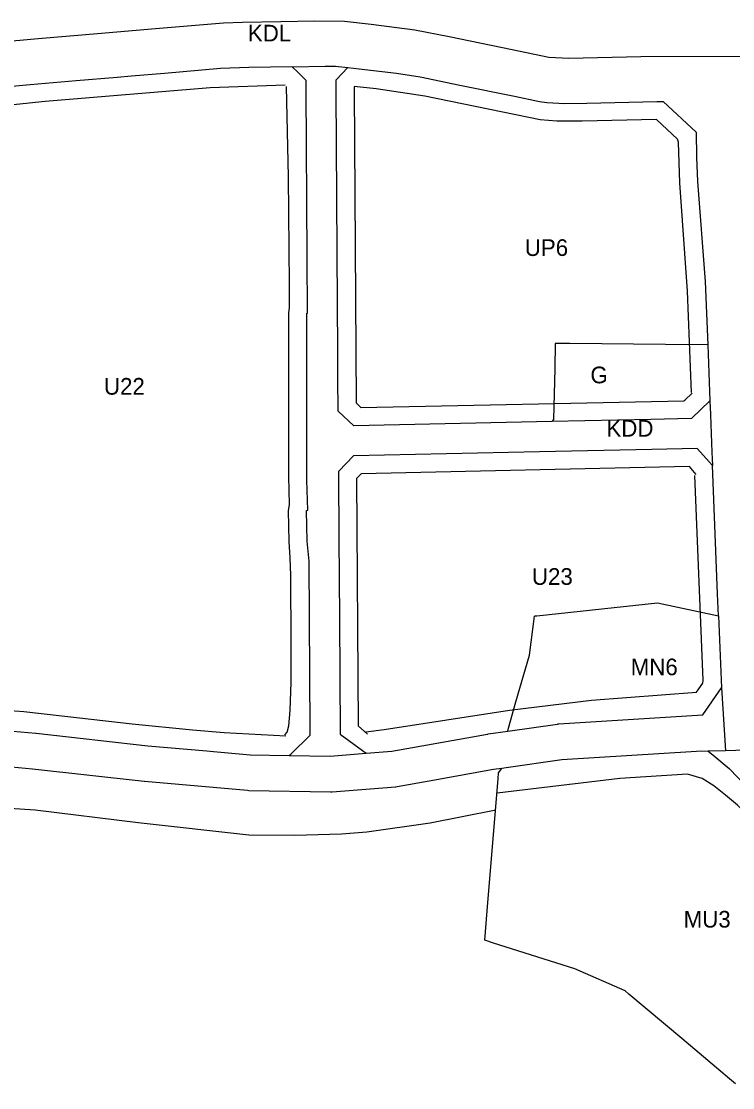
# Model space of a CAD drawing. Extents: x 7428080 to 7432143, y 5545880 to 5549217.
# Drawn here: x 7429649.7 to 7429886.6, y 5547932.8 to 5548287.9 of the extents above; entities that cross this region are included whole.
import ezdxf

# ---------------------------------------------------------------- set-up
doc = ezdxf.new("R2010")
doc.units = 0
for name, color, linetype in [('CZ_L_linie rozgraniczające tereny o różnym przeznaczeniu oraz różnych warunkach ich zabudowy i zagospodarowania', 7, 'Continuous'), ('CZ_L_maksymalne nieprzekraczalne linie zabudowy', 7, 'Continuous'), ('CZ_L_opisy_linie rozgraniczające tereny o różnym przeznaczeniu oraz różnych warunkach ich zabudowy i zagospodarowania', 7, 'Continuous')]:
    doc.layers.add(name, color=color, linetype=linetype)

msp = doc.modelspace()

# ---------------------------------------------------------------- linework, layer by layer
at = {"layer": 'CZ_L_linie rozgraniczające tereny o różnym przeznaczeniu oraz różnych warunkach ich zabudowy i zagospodarowania'}
for p, q in [((7429694.36, 5548285.36), (7429675.07, 5548283.73)), ((7429717.03, 5548287.27), (7429694.36, 5548285.36)), ((7429723.34, 5548287.55), (7429717.03, 5548287.27)), ((7429736.13, 5548287.76), (7429723.34, 5548287.55)), ((7429747.33, 5548287.89), (7429736.13, 5548287.76)), ((7429757.31, 5548287.88), (7429747.33, 5548287.89)), ((7429766.17, 5548286.78), (7429757.31, 5548287.88)), ((7429780.71, 5548284.89), (7429766.17, 5548286.78)), ((7429655.33, 5548282.07), (7429638.47, 5548280.52)), ((7429675.07, 5548283.73), (7429655.33, 5548282.07)), ((7429792.23, 5548282.72), (7429780.71, 5548284.89)), ((7429813.17, 5548278.42), (7429792.23, 5548282.72)), ((7429825.43, 5548275.82), (7429813.17, 5548278.42)), ((7429832.04, 5548275.52), (7429825.43, 5548275.82)), ((7429856.01, 5548276.02), (7429832.04, 5548275.52)), ((7429896.76, 5548276.15), (7429856.01, 5548276.02)), ((7429716.05, 5548272.14), (7429697.39, 5548270.56)), ((7429725.52, 5548272.55), (7429716.05, 5548272.14)), ((7429739.9, 5548272.77), (7429725.52, 5548272.55)), ((7429739.9, 5548272.77), (7429750.89, 5548272.94)), ((7429741.76, 5548270.94), (7429739.9, 5548272.77)), ((7429744.25, 5548268.5), (7429741.76, 5548270.94)), ((7429750.89, 5548272.94), (7429754.36, 5548272.91)), ((7429754.36, 5548272.91), (7429758.47, 5548272.5)), ((7429754.61, 5548268.4), (7429758.47, 5548272.5)), ((7429758.47, 5548272.5), (7429762.24, 5548272.12)), ((7429762.24, 5548272.12), (7429774.62, 5548270.6)), ((7429667.97, 5548268.08), (7429652.63, 5548266.79)), ((7429681.61, 5548269.23), (7429667.97, 5548268.08)), ((7429686.33, 5548269.63), (7429681.61, 5548269.23)), ((7429697.39, 5548270.56), (7429686.33, 5548269.63)), ((7429744.58, 5548268.17), (7429744.25, 5548268.5)), ((7429744.59, 5548265.02), (7429744.58, 5548268.17)), ((7429754.57, 5548268.33), (7429754.61, 5548268.4)), ((7429754.6, 5548264.4), (7429754.57, 5548268.33)), ((7429774.62, 5548270.6), (7429782.56, 5548269.4)), ((7429782.56, 5548269.4), (7429795.77, 5548266.68)), ((7429652.63, 5548266.79), (7429638.77, 5548265.45)), ((7429744.92, 5548209.33), (7429744.59, 5548265.02)), ((7429755.01, 5548193.74), (7429754.6, 5548264.4)), ((7429795.77, 5548266.68), (7429813.91, 5548262.93)), ((7429813.91, 5548262.93), (7429822.33, 5548261.15)), ((7429822.33, 5548261.15), (7429824.74, 5548260.84)), ((7429824.74, 5548260.84), (7429830.77, 5548260.56)), ((7429830.77, 5548260.56), (7429838.04, 5548260.62)), ((7429838.04, 5548260.62), (7429861.4, 5548261.14)), ((7429861.4, 5548261.14), (7429863.54, 5548261.2)), ((7429863.54, 5548261.2), (7429874.49, 5548250.98)), ((7429874.49, 5548250.98), (7429874.64, 5548242.67)), ((7429874.64, 5548242.67), (7429874.97, 5548234.56)), ((7429874.97, 5548234.56), (7429877.51, 5548201.27)), ((7429745.03, 5548190.75), (7429744.92, 5548209.33)), ((7429877.51, 5548201.27), (7429878.37, 5548180.2)), ((7429755.1, 5548178.47), (7429755.01, 5548193.74)), ((7429744.74, 5548190.74), (7429745.03, 5548190.75)), ((7429744.81, 5548172.97), (7429744.74, 5548190.74)), ((7429827.56, 5548180.61), (7429827.37, 5548172.29)), ((7429831.43, 5548180.58), (7429827.56, 5548180.61)), ((7429832.42, 5548180.57), (7429831.43, 5548180.58)), ((7429864.26, 5548180.31), (7429832.42, 5548180.57)), ((7429878.37, 5548180.2), (7429864.26, 5548180.31)), ((7429878.37, 5548180.2), (7429878.39, 5548180.2)), ((7429878.39, 5548180.2), (7429879.07, 5548161.45)), ((7429755.16, 5548169.12), (7429755.1, 5548178.47)), ((7429744.78, 5548155.01), (7429744.81, 5548172.97)), ((7429827.37, 5548172.29), (7429826.98, 5548155.26)), ((7429827.37, 5548172.29), (7429827.37, 5548172.29)), ((7429755.22, 5548158.09), (7429755.16, 5548169.12)), ((7429879.07, 5548161.45), (7429872.97, 5548155.6)), ((7429879.07, 5548161.45), (7429879.23, 5548156.91)), ((7429755.25, 5548158.07), (7429755.22, 5548158.09)), ((7429760.39, 5548153.18), (7429755.25, 5548158.07)), ((7429744.82, 5548135.11), (7429744.78, 5548155.01)), ((7429826.38, 5548154.6), (7429760.39, 5548153.18)), ((7429826.44, 5548154.6), (7429826.38, 5548154.6)), ((7429859.38, 5548155.31), (7429826.44, 5548154.6)), ((7429826.98, 5548155.26), (7429826.44, 5548154.6)), ((7429872.97, 5548155.6), (7429859.38, 5548155.31)), ((7429879.23, 5548156.91), (7429879.22, 5548156.89)), ((7429879.22, 5548156.89), (7429879.72, 5548144.43)), ((7429760.34, 5548143.18), (7429755.4, 5548138.09)), ((7429822.25, 5548144.51), (7429760.34, 5548143.18)), ((7429859.67, 5548145.31), (7429822.25, 5548144.51)), ((7429874.86, 5548145.64), (7429859.67, 5548145.31)), ((7429879.9, 5548139.96), (7429874.86, 5548145.64)), ((7429879.72, 5548144.43), (7429879.9, 5548139.96)), ((7429881.64, 5548097.22), (7429879.9, 5548139.96)), ((7429755.4, 5548138.09), (7429755.34, 5548138.02)), ((7429755.34, 5548138.02), (7429755.35, 5548137.21)), ((7429755.35, 5548137.21), (7429755.47, 5548115.72)), ((7429745.08, 5548125.11), (7429744.82, 5548135.11)), ((7429744.73, 5548125.02), (7429745.08, 5548125.11)), ((7429744.92, 5548114.8), (7429744.73, 5548125.02)), ((7429745.52, 5548108.07), (7429744.92, 5548114.8)), ((7429755.47, 5548115.72), (7429755.63, 5548089.2)), ((7429745.63, 5548089.1), (7429745.52, 5548108.07)), ((7429881.9, 5548089.88), (7429881.64, 5548097.22)), ((7429821.44, 5548089.88), (7429861.6, 5548094.22)), ((7429861.6, 5548094.22), (7429881.9, 5548089.88)), ((7429818.92, 5548076.81), (7429820.68, 5548089.84)), ((7429820.68, 5548089.84), (7429820.86, 5548089.85)), ((7429820.86, 5548089.85), (7429821.44, 5548089.88)), ((7429881.9, 5548089.88), (7429881.94, 5548089.87)), ((7429881.94, 5548089.87), (7429882.91, 5548065.97)), ((7429745.85, 5548051.97), (7429745.63, 5548089.1)), ((7429755.63, 5548089.2), (7429755.86, 5548050.51)), ((7429814.44, 5548061.27), (7429818.92, 5548076.81)), ((7429876.68, 5548056.89), (7429882.91, 5548065.97)), ((7429882.91, 5548065.97), (7429884.23, 5548044.99)), ((7429811.97, 5548052.44), (7429814.44, 5548061.27)), ((7429828.78, 5548053.92), (7429876.68, 5548056.89)), ((7429638.74, 5548052.22), (7429654.54, 5548050.78)), ((7429654.54, 5548050.78), (7429654.66, 5548050.77)), ((7429654.66, 5548050.77), (7429691.87, 5548046.65)), ((7429745.86, 5548050.11), (7429745.85, 5548051.97)), ((7429805.21, 5548050.55), (7429811.71, 5548051.49)), ((7429811.71, 5548051.49), (7429828.3, 5548053.87)), ((7429811.71, 5548051.49), (7429811.97, 5548052.44)), ((7429828.3, 5548053.87), (7429828.51, 5548053.89)), ((7429828.51, 5548053.89), (7429828.78, 5548053.92)), ((7429739.41, 5548043.88), (7429745.86, 5548050.11)), ((7429755.86, 5548050.51), (7429763.31, 5548045.02)), ((7429773.06, 5548044.78), (7429805, 5548050.52)), ((7429805, 5548050.52), (7429805.03, 5548050.53)), ((7429805.03, 5548050.53), (7429805.21, 5548050.55)), ((7429691.87, 5548046.65), (7429711.48, 5548044.92)), ((7429711.48, 5548044.92), (7429713.65, 5548044.73)), ((7429713.65, 5548044.73), (7429725.9, 5548043.65)), ((7429725.9, 5548043.65), (7429738.94, 5548043.42)), ((7429738.94, 5548043.42), (7429739.41, 5548043.88)), ((7429752.6, 5548043.18), (7429764.55, 5548044.11)), ((7429763.31, 5548045.02), (7429764.55, 5548044.11)), ((7429764.55, 5548044.11), (7429773.06, 5548044.78)), ((7429874.55, 5548044.74), (7429829.76, 5548041.95)), ((7429878.53, 5548044.84), (7429874.55, 5548044.74)), ((7429884.23, 5548044.99), (7429878.53, 5548044.84)), ((7429878.53, 5548044.84), (7429879.98, 5548043.63)), ((7429879.98, 5548043.63), (7429885.45, 5548039.08)), ((7429896.47, 5548045.31), (7429884.23, 5548044.99)), ((7429653.39, 5548038.84), (7429638.05, 5548040.23)), ((7429738.94, 5548043.42), (7429752.6, 5548043.18)), ((7429829.76, 5548041.95), (7429811.16, 5548039.29)), ((7429690.62, 5548034.71), (7429653.39, 5548038.84)), ((7429807.01, 5548038.69), (7429785.55, 5548034.83)), ((7429809.79, 5548039.09), (7429807.01, 5548038.69)), ((7429808.49, 5548035.65), (7429808.66, 5548037.66)), ((7429808.66, 5548037.66), (7429809.79, 5548039.09)), ((7429811.16, 5548039.29), (7429809.79, 5548039.09)), ((7429885.45, 5548039.08), (7429885.51, 5548039.03)), ((7429885.51, 5548039.03), (7429885.56, 5548038.98)), ((7429885.56, 5548038.98), (7429891.05, 5548033.33)), ((7429690.74, 5548034.7), (7429690.62, 5548034.71)), ((7429690.75, 5548034.7), (7429690.74, 5548034.7)), ((7429725.05, 5548031.68), (7429690.75, 5548034.7)), ((7429774.85, 5548032.91), (7429774.46, 5548032.86)), ((7429774.89, 5548032.92), (7429774.85, 5548032.91)), ((7429785.55, 5548034.83), (7429774.89, 5548032.92)), ((7429805.08, 5547994.44), (7429808.49, 5548035.65)), ((7429725.43, 5548031.66), (7429725.05, 5548031.68)), ((7429725.47, 5548031.66), (7429725.43, 5548031.66)), ((7429752.68, 5548031.18), (7429725.47, 5548031.66)), ((7429753.03, 5548031.18), (7429752.68, 5548031.18)), ((7429753.25, 5548031.19), (7429753.03, 5548031.18)), ((7429774.3, 5548032.84), (7429753.25, 5548031.19)), ((7429774.46, 5548032.86), (7429774.3, 5548032.84)), ((7429804.04, 5547981.84), (7429805.08, 5547994.44)), ((7429807.02, 5547980.89), (7429804.04, 5547981.84)), ((7429834.03, 5547972.32), (7429807.02, 5547980.89)), ((7429850.81, 5547964.96), (7429834.03, 5547972.32)), ((7429852.03, 5547963.93), (7429850.81, 5547964.96)), ((7429869.68, 5547949.11), (7429852.03, 5547963.93)), ((7429885.61, 5547935.73), (7429869.68, 5547949.11)), ((7429887.63, 5547934.07), (7429885.61, 5547935.73))]:
    msp.add_line(p, q, dxfattribs=at)
at = {"layer": 'CZ_L_maksymalne nieprzekraczalne linie zabudowy'}
for points in [[(7429737.56, 5548266.68), (7429712.6, 5548265.77), (7429657.63, 5548261.19), (7429626.79, 5548257.94), (7429606.97, 5548255.66), (7429606.31, 5548255.44), (7429604.61, 5548253.44), (7429611.04, 5548115.65), (7429608.73, 5548101.41), (7429605.47, 5548096.04), (7429602.01, 5548092.86), (7429597.64, 5548091.02), (7429592.48, 5548090.26), (7429591.2, 5548089.04), (7429593.66, 5548052.51), (7429625.28, 5548059.08), (7429626.81, 5548059.19), (7429638.42, 5548058.91), (7429650.51, 5548058.04), (7429686.57, 5548053.92), (7429706.66, 5548051.95), (7429717.21, 5548051.09), (7429737.76, 5548049.93)], [(7429737.45, 5548050.25), (7429738.27, 5548051.21), (7429738.79, 5548053.26), (7429739.27, 5548058.34), (7429739.55, 5548067.83), (7429739.62, 5548080.54), (7429739.42, 5548103.35), (7429739.26, 5548109.2), (7429738.93, 5548114.65), (7429738.73, 5548124.86), (7429739, 5548127.02), (7429738.82, 5548136.27), (7429738.75, 5548190.8), (7429738.98, 5548192.45), (7429738.97, 5548200.12), (7429738.73, 5548236.11), (7429737.99, 5548266.23)], [(7429760.71, 5548266.12), (7429760.6, 5548266), (7429760.59, 5548264.88), (7429761.21, 5548160.82), (7429762.73, 5548159.23), (7429870.33, 5548161.55), (7429870.71, 5548161.75), (7429873.17, 5548164.1)], [(7429872.95, 5548164.33), (7429871.64, 5548197.99), (7429868.99, 5548234.11), (7429868.58, 5548247.64), (7429868.21, 5548248.63), (7429861.23, 5548255.14), (7429836.47, 5548254.61), (7429828.05, 5548254.68), (7429822.49, 5548255.08), (7429784.05, 5548262.97), (7429767.84, 5548265.39), (7429760.61, 5548266.22)], [(7429874.5, 5548137.01), (7429872.22, 5548139.58), (7429762.93, 5548137.23), (7429761.35, 5548135.61), (7429761.84, 5548053.26), (7429765.04, 5548050.49)], [(7429764.44, 5548051.22), (7429770.59, 5548052), (7429812.33, 5548058.52), (7429839.61, 5548061.76), (7429874.6, 5548064.53), (7429876.65, 5548067.48), (7429876.8, 5548068.43), (7429874.04, 5548136.6)], [(7429903.91, 5547892.99), (7429913.69, 5547902.98), (7429949.06, 5547940.49), (7429953.99, 5547945.43), (7429955.85, 5547947.81), (7429942.43, 5547966.54), (7429930.2, 5547982.28), (7429925.26, 5547988.19), (7429907.39, 5548007.36), (7429891.98, 5548023.22), (7429888.21, 5548026.79), (7429884.28, 5548030.22), (7429880.32, 5548033.27), (7429876.46, 5548035.7), (7429871.54, 5548037.22), (7429849.06, 5548035.69), (7429808.16, 5548030.84)], [(7429807.79, 5548025.22), (7429785.86, 5548020.87), (7429764.76, 5548017.83), (7429756.34, 5548017.17), (7429740.83, 5548016.75), (7429725.46, 5548016.89), (7429688.59, 5548020.99), (7429654.28, 5548025.17), (7429644.09, 5548025.88)]]:
    msp.add_lwpolyline(points, dxfattribs=at)

# ---------------------------------------------------------------- texts
at = {"layer": 'CZ_L_opisy_linie rozgraniczające tereny o różnym przeznaczeniu oraz różnych warunkach ich zabudowy i zagospodarowania'}
for s, height, p in [('KDL', 5.549, (7429725.15, 5548281.19)), ('UP6', 5.549, (7429817.39, 5548209.75)), ('G', 5.55, (7429839.26, 5548167.34)), ('U22', 5.549, (7429677.21, 5548163.56)), ('KDD', 5.549, (7429844.59, 5548149.57)), ('U23', 5.549, (7429819.77, 5548100.22)), ('MN6', 5.549, (7429852.68, 5548070.11)), ('MU3', 5.549, (7429870.31, 5547986.09))]:
    msp.add_text(s, height=height, dxfattribs=at).set_placement(p)

doc.saveas('drawing.dxf')
